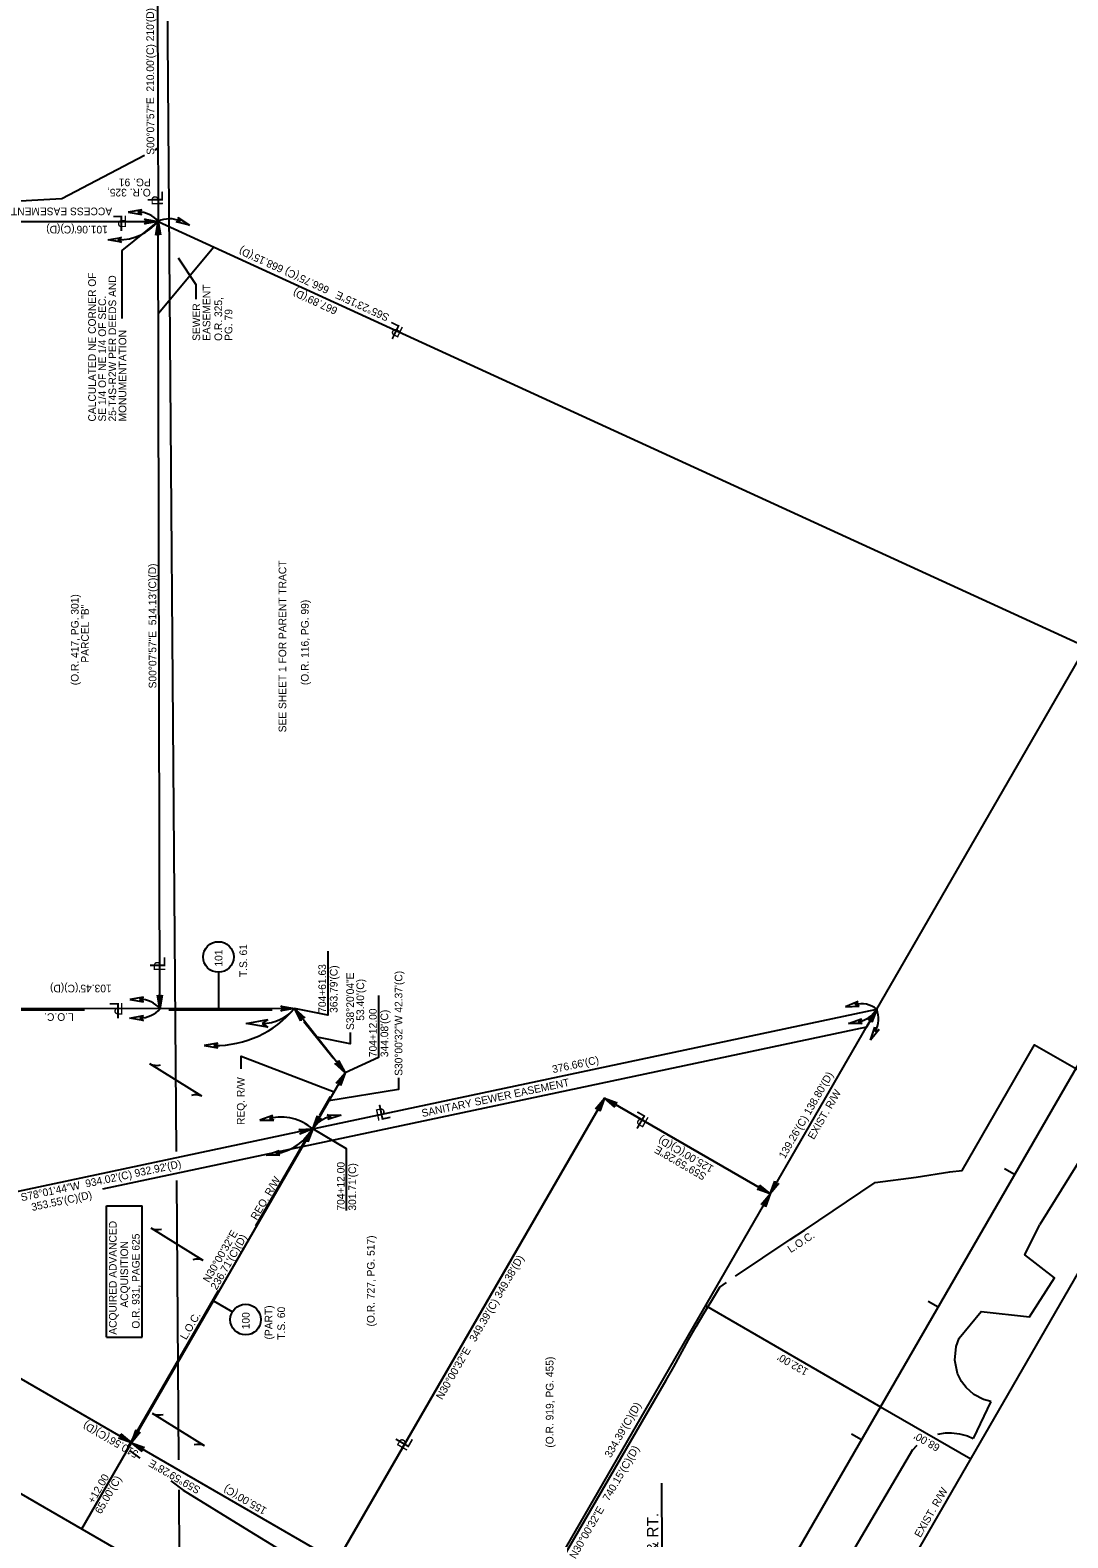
# Model space of a CAD drawing. Extents: x 2003883 to 2008298, y 399149 to 424047.
# Drawn here: x 2006444 to 2007122, y 402845 to 403830 of the extents above; entities that cross this region are included whole.
import ezdxf

# ---------------------------------------------------------------- set-up
doc = ezdxf.new("R2010")
doc.units = 0
for name, color, linetype in [('BaselineFlagLT', 7, 'Continuous'), ('BaselineSurvey', 7, 'Continuous'), ('BaselineTextWt1', 7, 'Continuous'), ('ConstLimits', 7, 'Continuous'), ('ConstLimitsText', 7, 'Continuous'), ('DataBoxWt1', 7, 'Continuous'), ('EaseLine_ep', 7, 'Continuous'), ('EaseLineText_ep', 7, 'Continuous'), ('GovTwpRgeLine_ep', 7, 'Continuous'), ('ParcelBubble100', 7, 'Continuous'), ('PropertyLine_ep', 7, 'Continuous'), ('PropertyLineHook_ep', 7, 'Continuous'), ('PropertyLineSymbol_ep', 7, 'Continuous'), ('PropertyLineText_ep', 7, 'Continuous'), ('RWandLA_StaTie', 7, 'Continuous'), ('RWandLA_Text', 7, 'Continuous'), ('RWandLA_Text_ep', 7, 'Continuous'), ('RWandLA_WidthArrow_ep', 7, 'Continuous'), ('RWLine', 7, 'Continuous'), ('RWLine_ep', 7, 'Continuous'), ('TextMisc', 7, 'Continuous')]:
    doc.layers.add(name, color=color, linetype=linetype)

msp = doc.modelspace()

# ---------------------------------------------------------------- linework, layer by layer
at = {"layer": 'BaselineFlagLT'}
msp.add_lwpolyline([(2006720.56, 402711.11), (2006857.82, 402747.44), (2006857.19, 402881.05)], dxfattribs=at)
at = {"layer": 'BaselineSurvey'}
for p, q in [((2006836.17, 402647.34), (2007687.69, 404121.69)), ((2007087.53, 403082.55), (2007081.03, 403086.3)), ((2007037.52, 402995.96), (2007031.02, 402999.71)), ((2006832.62, 402646.39), (2006307.25, 402949.82)), ((2006987.5, 402909.36), (2006981.01, 402913.11))]:
    msp.add_line(p, q, dxfattribs=at)
at = {"layer": 'ConstLimits'}
msp.add_line((2007072.12, 402934.43), (2007060.41, 402910.34), dxfattribs=at)
for points in [[(2006479.85, 403190), (2006332.39, 403189.92)], [(2006602.54, 403190.06), (2006534.92, 403190.03)], [(2006642.33, 403158.63), (2006623.31, 403182.39)], [(2006905.28, 403016.26), (2006940.92, 403040.2), (2006950.33, 403046.31), (2006996.49, 403077.39), (2006996.49, 403077.39), (2007023.29, 403080.85), (2007045.15, 403084.36), (2007045.15, 403084.36), (2007053.2, 403085.31), (2007100.64, 403167.34), (2007156.96, 403135.14), (2007104.02, 403049.96)], [(2006633.63, 403121.45), (2006640.69, 403133.68)], [(2006591.85, 403049.14), (2006627.04, 403110.05)], [(2007072.12, 402934.43), (2007067.25, 402935.81), (2007061.02, 402939.07), (2007055.84, 402943.62), (2007052.96, 402947.42), (2007050.32, 402952.69), (2007048.48, 402961.33), (2007049.37, 402970.38), (2007051.41, 402975.84), (2007065.81, 402993.18), (2007097.27, 402989.65), (2007113.66, 403015.13), (2007094.19, 403030.17), (2007104.02, 403049.96)], [(2006508.46, 402904.84), (2006567.38, 403006.81)], [(2006753.23, 402764.67), (2006753.23, 402764.67), (2006753.16, 402764.53), (2006859.92, 402948.4), (2006864.89, 402957.08), (2006874.47, 402974.64), (2006879.44, 402983.32), (2006884.6, 402991.89), (2006889.78, 403000.45), (2006894.93, 403009.02), (2006894.93, 403009.02), (2006899.45, 403012.18)], [(2007037.4, 402913.02), (2007042.49, 402913.89), (2007046.27, 402914.01), (2007051.65, 402913.4), (2007056.84, 402911.93), (2007060.41, 402910.34)], [(2006509.29, 402902.4), (2006516.17, 402897.33)], [(2006943.48, 402771.38), (2007021.09, 402903.08)], [(2007020.8, 402902.7), (2007023.97, 402905.97)], [(2006536.26, 402882.53), (2006544.33, 402876.58), (2006584.64, 402851.71), (2006635.87, 402820.4), (2006644.5, 402815.35), (2006653.07, 402810.19), (2006670.21, 402799.88), (2006678.78, 402794.72), (2006695.88, 402784.33), (2006704.42, 402779.13), (2006721.46, 402768.64), (2006729.97, 402763.38), (2006732.89, 402761.57)]]:
    msp.add_lwpolyline(points, dxfattribs=at)
at = {"layer": 'DataBoxWt1'}
for p, q in [((2006494.37, 402976.47), (2006494.37, 403062.21)), ((2006494.37, 403062.21), (2006517.5, 403062.21)), ((2006517.5, 402976.47), (2006517.5, 403062.21)), ((2006494.37, 402976.47), (2006517.5, 402976.47))]:
    msp.add_line(p, q, dxfattribs=at)
at = {"layer": 'EaseLine_ep'}
for p, q in [((2006465.05, 403720.02), (2006519.13, 403748.19)), ((2006526.13, 403751.83), (2006527.94, 403752.78)), ((2006302.99, 403711.05), (2006465.05, 403720.02)), ((2006528.19, 403645.01), (2006564.42, 403688.35)), ((2006997.46, 403190.54), (2006990.71, 403178.84)), ((2006990.71, 403178.84), (2006491.7, 403073.04))]:
    msp.add_line(p, q, dxfattribs=at)
at = {"layer": 'EaseLineText_ep'}
msp.add_lwpolyline([(2006552.87, 403654.27), (2006552.87, 403663.58), (2006541.27, 403680.98)], dxfattribs=at)
at = {"layer": 'GovTwpRgeLine_ep'}
for p, q in [((2006540.01, 403097.66), (2006528.59, 404563.92)), ((2006541.57, 402896.23), (2006540.15, 403078.81)), ((2006542.09, 402831.09), (2006541.73, 402876.66))]:
    msp.add_line(p, q, dxfattribs=at)
at = {"layer": 'ParcelBubble100'}
for centre in [(2006567.42, 403224.68), (2006585.2, 402987.87)]:
    msp.add_circle(centre, 10, dxfattribs=at)
at = {"layer": 'PropertyLine_ep'}
for p, q in [((2006527.56, 403915.01), (2006528.05, 403705.01)), ((2006426.99, 403705.03), (2006528.05, 403705.01)), ((2006528.05, 403705.01), (2007134.22, 403427.32)), ((2006529.24, 403190.88), (2006528.05, 403705.01)), ((2006629, 403112.41), (2006997.46, 403190.54)), ((2006644.81, 402829.92), (2006819.55, 403132.47)), ((2006819.57, 403132.47), (2006644.83, 402829.91)), ((2006819.55, 403132.47), (2006927.81, 403069.95)), ((2006927.82, 403069.95), (2006819.57, 403132.47)), ((2006629, 403112.41), (2006166.22, 403014.29))]:
    msp.add_line(p, q, dxfattribs=at)
at = {"layer": 'PropertyLineHook_ep'}
for p, q in [((2006556.61, 403133.7), (2006522.67, 403154.88)), ((2006557.45, 403026.43), (2006523.51, 403047.6)), ((2006558.39, 402905.47), (2006524.45, 402926.64))]:
    msp.add_line(p, q, dxfattribs=at)
for centre, start, end in [((2006526.89, 403163.43), 243.73036, 285.75196), ((2006552.49, 403125.1), 64.39507, 106.41667), ((2006527.73, 403056.15), 243.73036, 285.75196), ((2006553.33, 403017.83), 64.39507, 106.41667), ((2006528.67, 402935.2), 243.73036, 285.75196), ((2006554.27, 402896.87), 64.39507, 106.41667)]:
    msp.add_arc(centre, 9.54, start, end, dxfattribs=at)
at = {"layer": 'PropertyLineText_ep'}
for p, q in [((2006517.33, 403712.54), (2006508.43, 403711.04)), ((2006508.45, 403711.06), (2006517.35, 403709.51)), ((2006514.95, 403711.06), (2006517.35, 403712.56)), ((2006517.35, 403709.51), (2006514.95, 403711.06)), ((2006519.2, 403706.56), (2006528.05, 403705.01)), ((2006521.6, 403705.01), (2006519.2, 403706.56)), ((2006541.01, 403707.54), (2006548.46, 403702.52)), ((2006542.57, 403705.15), (2006541.01, 403707.54)), ((2006528.05, 403705.01), (2006519.2, 403703.46)), ((2006519.2, 403703.46), (2006521.6, 403705.01)), ((2006526.52, 403696.15), (2006528.05, 403705.01)), ((2006528.06, 403698.56), (2006526.52, 403696.15)), ((2006528.05, 403705.01), (2006529.62, 403696.16)), ((2006529.62, 403696.16), (2006528.06, 403698.56)), ((2006539.75, 403704.71), (2006542.57, 403705.15)), ((2006548.46, 403702.52), (2006539.75, 403704.71)), ((2006495.32, 403692.92), (2006504.17, 403694.47)), ((2006504.17, 403691.37), (2006495.32, 403692.92)), ((2006504.17, 403694.47), (2006501.77, 403692.92)), ((2006501.77, 403692.92), (2006504.17, 403691.37)), ((2006518.52, 403198.42), (2006509.62, 403196.92)), ((2006509.64, 403196.93), (2006518.54, 403195.38)), ((2006516.14, 403196.93), (2006518.54, 403198.43)), ((2006518.54, 403195.38), (2006516.14, 403196.93)), ((2006529.24, 403190.88), (2006527.67, 403199.72)), ((2006527.67, 403199.72), (2006529.22, 403197.33)), ((2006529.22, 403197.33), (2006530.77, 403199.73)), ((2006530.77, 403199.73), (2006529.24, 403190.88)), ((2006985.36, 403195.57), (2006977, 403192.17)), ((2006983.36, 403193.6), (2006985.38, 403195.58)), ((2006986.04, 403192.61), (2006983.36, 403193.6)), ((2006509.59, 403184.83), (2006518.44, 403186.38)), ((2006518.44, 403183.28), (2006509.59, 403184.83)), ((2006518.44, 403186.38), (2006516.04, 403184.83)), ((2006516.04, 403184.83), (2006518.44, 403183.28)), ((2006977.02, 403192.19), (2006986.04, 403192.61)), ((2006979.08, 403181.35), (2006987.55, 403184.33)), ((2006987.55, 403184.33), (2006985.44, 403182.4)), ((2006988.06, 403181.27), (2006979.08, 403181.35)), ((2006985.44, 403182.4), (2006988.06, 403181.27)), ((2006993.42, 403170.38), (2006996.27, 403178.9)), ((2006999, 403177.42), (2006993.42, 403170.38)), ((2006996.27, 403178.9), (2006996.49, 403176.05)), ((2006996.49, 403176.05), (2006999, 403177.42)), ((2006638.54, 403121.55), (2006647.52, 403121.34)), ((2006641.14, 403120.37), (2006638.54, 403121.55)), ((2006647.52, 403121.34), (2006639, 403118.48)), ((2006639, 403118.48), (2006641.14, 403120.37)), ((2006620.02, 403112.1), (2006629, 403112.41)), ((2006622.69, 403111.08), (2006620.02, 403112.1)), ((2006629, 403112.41), (2006620.66, 403109.06)), ((2006620.66, 403109.06), (2006622.69, 403111.08)), ((2006598.6, 403095.29), (2006607.09, 403098.22)), ((2006607.58, 403095.16), (2006598.6, 403095.29)), ((2006607.09, 403098.22), (2006604.96, 403096.31)), ((2006604.96, 403096.31), (2006607.58, 403095.16))]:
    msp.add_line(p, q, dxfattribs=at)
for centre, radius, start, end in [((2006515.59, 403695.2), 15.86, 38.19432, 92.38767), ((2006535.45, 403689.64), 17.06, 65.60387, 115.71277), ((2006502.01, 403727.04), 34.11, 269.65455, 319.76346), ((2006516.78, 403181.07), 15.86, 38.19432, 92.38767), ((2006987.43, 403178.26), 15.86, 50.74651, 104.93986), ((2006516.22, 403201.9), 17.06, 269.65455, 319.76346), ((2006982.81, 403199.27), 17.06, 279.10941, 329.21831), ((2006981.57, 403184.35), 17.06, 331.18389, 21.2928), ((2006643.52, 403103.47), 17.06, 98.27039, 148.37929), ((2006599.79, 403130.04), 34.11, 278.79159, 328.90049)]:
    msp.add_arc(centre, radius, start, end, dxfattribs=at)
at = {"layer": 'RWandLA_StaTie'}
msp.add_line((2006478.1, 402851.15), (2006510.61, 402907.43), dxfattribs=at)
at = {"layer": 'RWandLA_Text'}
for p, q in [((2006567.44, 403214.68), (2006567.47, 403190.93)), ((2006585.63, 403181.31), (2006599.79, 403183.79)), ((2006599.79, 403183.79), (2006595.95, 403181.31)), ((2006610.62, 403190.98), (2006608.21, 403192.53)), ((2006608.21, 403192.53), (2006617.07, 403190.99)), ((2006617.07, 403190.99), (2006608.22, 403189.43)), ((2006608.22, 403189.43), (2006610.62, 403190.98)), ((2006621.34, 403183.09), (2006617.07, 403190.99)), ((2006617.07, 403190.99), (2006623.77, 403185.01)), ((2006623.77, 403185.01), (2006621.07, 403185.93)), ((2006621.07, 403185.93), (2006621.34, 403183.09)), ((2006599.79, 403178.83), (2006585.63, 403181.31)), ((2006595.95, 403181.31), (2006599.79, 403178.83)), ((2006566.97, 403168.33), (2006558.07, 403166.83)), ((2006558.1, 403166.85), (2006567, 403165.3)), ((2006564.6, 403166.85), (2006567, 403168.35)), ((2006567, 403165.3), (2006564.6, 403166.85)), ((2006650.19, 403149.11), (2006643.48, 403155.09)), ((2006643.48, 403155.09), (2006646.19, 403154.17)), ((2006646.19, 403154.17), (2006645.91, 403157.01)), ((2006645.91, 403157.01), (2006650.19, 403149.11)), ((2006644.42, 403142.22), (2006650.19, 403149.11)), ((2006650.19, 403149.11), (2006647.1, 403140.67)), ((2006646.96, 403143.52), (2006644.42, 403142.22)), ((2006647.1, 403140.67), (2006646.96, 403143.52)), ((2006602.98, 403121.2), (2006594.53, 403118.04)), ((2006594.55, 403118.05), (2006603.59, 403118.22)), ((2006600.93, 403119.29), (2006603.01, 403121.22)), ((2006603.59, 403118.22), (2006600.93, 403119.29)), ((2006629, 403112.41), (2006632.08, 403120.85)), ((2006634.76, 403119.3), (2006629, 403112.41)), ((2006632.08, 403120.85), (2006632.22, 403118)), ((2006632.22, 403118), (2006634.76, 403119.3)), ((2006623.16, 403105.58), (2006629, 403112.41)), ((2006625.72, 403106.86), (2006623.16, 403105.58)), ((2006625.83, 403104), (2006625.72, 403106.86)), ((2006629, 403112.41), (2006625.83, 403104)), ((2006564.1, 403000.05), (2006576.54, 402992.87)), ((2006502.17, 402910.52), (2006505.02, 402910.66)), ((2006510.61, 402907.43), (2006502.17, 402910.52)), ((2006505.02, 402910.66), (2006503.72, 402913.2)), ((2006503.72, 402913.2), (2006510.61, 402907.43)), ((2006510.61, 402907.43), (2006513.69, 402915.87)), ((2006516.38, 402914.32), (2006510.61, 402907.43)), ((2006513.69, 402915.87), (2006513.83, 402913.02)), ((2006513.83, 402913.02), (2006516.38, 402914.32)), ((2006510.61, 402907.43), (2006519.05, 402904.35)), ((2006517.5, 402901.66), (2006510.61, 402907.43)), ((2006519.05, 402904.35), (2006516.19, 402904.21)), ((2006516.19, 402904.21), (2006517.5, 402901.66))]:
    msp.add_line(p, q, dxfattribs=at)
for points in [[(2006638.92, 403228.45), (2006638.92, 403186.63), (2006617.07, 403190.99)], [(2006672.04, 403199.43), (2006672.04, 403159.01), (2006650.19, 403149.11)], [(2006653.59, 403175.46), (2006653.59, 403167.98), (2006631.84, 403172.31)], [(2006582.27, 403151.68), (2006582.27, 403159.81), (2006643.03, 403136.71)], [(2006685.1, 403145.73), (2006685.1, 403138.25), (2006639.59, 403130.76)], [(2006651.03, 403059.06), (2006651.03, 403099.35), (2006629, 403112.41)]]:
    msp.add_lwpolyline(points, dxfattribs=at)
for centre, radius, start, end in [((2006564.98, 403235.06), 68.23, 269.65455, 319.76346), ((2006596.23, 403208.62), 27.29, 269.65455, 319.76346), ((2006608.25, 403088.42), 31.72, 49.15233, 103.34569)]:
    msp.add_arc(centre, radius, start, end, dxfattribs=at)
at = {"layer": 'RWandLA_Text_ep'}
for p, q in [((2006991.7, 403183.65), (2006997.46, 403190.54)), ((2006994.24, 403184.96), (2006991.7, 403183.65)), ((2006994.38, 403182.1), (2006994.24, 403184.96)), ((2006997.46, 403190.54), (2006994.38, 403182.1)), ((2006813.8, 403125.58), (2006819.57, 403132.47)), ((2006816.35, 403126.88), (2006813.8, 403125.58)), ((2006816.49, 403124.03), (2006816.35, 403126.88)), ((2006819.57, 403132.47), (2006816.49, 403124.03)), ((2006826.46, 403126.7), (2006819.57, 403132.47)), ((2006819.57, 403132.47), (2006828.01, 403129.38)), ((2006828.01, 403129.38), (2006825.16, 403129.24)), ((2006825.16, 403129.24), (2006826.46, 403126.7)), ((2006920.93, 403075.72), (2006927.82, 403069.95)), ((2006922.23, 403073.17), (2006920.93, 403075.72)), ((2006927.82, 403069.95), (2006930.9, 403078.39)), ((2006933.58, 403076.84), (2006927.82, 403069.95)), ((2006930.9, 403078.39), (2006931.04, 403075.53)), ((2006931.04, 403075.53), (2006933.58, 403076.84)), ((2006919.38, 403073.03), (2006922.23, 403073.17)), ((2006927.82, 403069.95), (2006919.38, 403073.03)), ((2006922.05, 403063.06), (2006927.82, 403069.95)), ((2006927.82, 403069.95), (2006924.73, 403061.51)), ((2006924.59, 403064.36), (2006922.05, 403063.06)), ((2006924.73, 403061.51), (2006924.59, 403064.36))]:
    msp.add_line(p, q, dxfattribs=at)
msp.add_lwpolyline([(2006504.6, 403641.67), (2006504.6, 403686), (2006528.05, 403705.01)], dxfattribs=at)
at = {"layer": 'RWandLA_WidthArrow_ep'}
for p, q in [((2006885.7, 402997.03), (2007000, 402931.01)), ((2007000, 402931.01), (2007058.89, 402897))]:
    msp.add_line(p, q, dxfattribs=at)
at = {"layer": 'RWLine'}
for p, q in [((2006617.07, 403190.99), (2006114.83, 403190.33)), ((2006650.19, 403149.11), (2006617.07, 403190.99)), ((2006510.61, 402907.43), (2006650.19, 403149.11)), ((2006510.61, 402907.43), (2006297.96, 403030.25)), ((2006740.08, 402774.9), (2006510.61, 402907.43))]:
    msp.add_line(p, q, dxfattribs=at)
at = {"layer": 'RWLine_ep'}
for p, q in [((2006760.57, 402780.38), (2007323.32, 403754.74)), ((2006296.18, 401576.43), (2007496.51, 403654.71))]:
    msp.add_line(p, q, dxfattribs=at)

# ---------------------------------------------------------------- texts
at = {"layer": 'BaselineTextWt1'}
msp.add_text('ACQUISITION LT. & RT.', height=7.5, rotation=90, dxfattribs=at).set_placement((2006854.87, 402750.81))
at = {"layer": 'ConstLimitsText'}
for rotation, p in [(180.07577, (2006472.91, 403187.97)), (33.01404, (2006941.26, 403031.24)), (59.9787, (2006546.34, 402974.27))]:
    msp.add_text('L.O.C.', height=5, rotation=rotation, dxfattribs=at).set_placement(p)
at = {"layer": 'EaseLineText_ep'}
for s, rotation, p in [('O.R. 325,', 179.9919, (2006523.2, 403726.32)), ('PG. 91', 179.9919, (2006523.2, 403732.99)), ('ACCESS EASEMENT', 179.9919, (2006498, 403714.06)), ('EASEMENT', 89.9919, (2006562.17, 403627.02)), ('SEWER', 89.9919, (2006555.49, 403627.02)), ('O.R. 325,', 89.9919, (2006569.83, 403626.99)), ('PG. 79', 89.9919, (2006576.51, 403626.99)), ('SANITARY SEWER EASEMENT', 11.9711, (2006700.73, 403120.13))]:
    msp.add_text(s, height=5, rotation=rotation, dxfattribs=at).set_placement(p)
at = {"layer": 'ParcelBubble100'}
for s, p in [('101', (2006570.02, 403218.38)), ('100', (2006587.8, 402981.57))]:
    msp.add_text(s, height=5, rotation=90, dxfattribs=at).set_placement(p)
at = {"layer": 'PropertyLineSymbol_ep'}
for s, height, rotation, p in [('L', 10, 91.09018, (2006531.3, 403717.57)), ('P', 7.5, 91.09018, (2006531.29, 403715.47)), ('L', 10, 179.99193, (2006505.76, 403708.82)), ('P', 7.5, 179.99193, (2006507.86, 403708.77)), ('L', 10, 154.1926, (2006686.86, 403636.52)), ('P', 7.5, 154.1926, (2006688.73, 403635.56)), ('L', 10, 89.85413, (2006532.76, 403217.45)), ('P', 7.5, 89.85413, (2006532.7, 403215.35)), ('L', 10, 180.08006, (2006503.46, 403194.65)), ('P', 7.5, 180.08006, (2006505.56, 403194.6)), ('P', 7.5, 11.9711, (2006670.98, 403117.62)), ('L', 10, 11.9711, (2006673.05, 403118.01)), ('L', 10, 149.99618, (2006847.39, 403120.46)), ('P', 7.5, 149.99618, (2006849.18, 403119.37)), ('L', 10, 59.99111, (2006691.1, 402903.35)), ('P', 7.5, 59.99111, (2006690.01, 402901.56))]:
    msp.add_text(s, height=height, rotation=rotation, dxfattribs=at).set_placement(p)
at = {"layer": 'PropertyLineText_ep'}
for s, rotation, p in [('S00°07\'57"E  210.00\'(C) 210\'(D)', 90.13252, (2006525.51, 403748.54)), ("101.06'(C)(D)", 179.96966, (2006495.21, 403702.16)), ('S65°23\'15"E   666.75\'(C) 668.15\'(D)', 155.38743, (2006679.53, 403644.07)), ('CALCULATED NE CORNER OF', 90, (2006487.35, 403574.35)), ('25-T4S-R2W PER DEEDS AND', 90, (2006500.61, 403574.35)), ("667.89'(D)", 155.38743, (2006645.74, 403648.45)), ('SE 1/4 OF NE 1/4 OF SEC.', 90, (2006493.98, 403574.35)), ('MONUMENTATION', 90, (2006507.25, 403574.35)), ('S00°07\'57"E  514.13\'(C)(D)', 90.13252, (2006526.9, 403400.08)), ('SEE SHEET 1 FOR PARENT TRACT', 90, (2006611.73, 403371.38)), ('(O.R. 417, PG. 301)', 90, (2006476.07, 403402.14)), ('PARCEL "B"', 90, (2006482.75, 403416.89)), ('(O.R. 116, PG. 99)', 90, (2006626.38, 403402.21)), ("103.45'(C)(D)", 180.07577, (2006497.69, 403206.62)), ("376.66'(C)", 11.9711, (2006786.05, 403148.8)), ('S78°01\'44"W  934.02\'(C) 932.92\'(D)', 11.9711, (2006438.84, 403065.17)), ("353.55'(C)(D)", 11.9711, (2006445.78, 403058.78)), ('(O.R. 727, PG. 517)', 90, (2006669.46, 402983.39)), ('N30°00\'32"E   349.39\'(C) 349.38\'(D)', 59.99111, (2006713.54, 402935.18)), ('(O.R. 919, PG. 455)', 90, (2006786.31, 402904.25))]:
    msp.add_text(s, height=5, rotation=rotation, dxfattribs=at).set_placement(p)
at = {"layer": 'RWandLA_Text'}
for s, rotation, p in [('T.S. 61', 90, (2006586.16, 403211.56)), ('704+61.63', 90, (2006637.72, 403188.2)), ("363.79'(C)", 90, (2006645.22, 403188.2)), ('S38°20\'04"E', 90, (2006655.98, 403176.99)), ('S30°00\'32"W 42.37\'(C)', 90, (2006687.61, 403147.07)), ("53.40'(C)", 90, (2006662.62, 403183.08)), ('704+12.00', 90, (2006670.84, 403159.26)), ("344.08'(C)", 90, (2006678.34, 403159.26)), ('REQ. R/W', 90, (2006584.51, 403114.97)), ('704+12.00', 90, (2006649.86, 403059.06)), ("301.71'(C)", 90, (2006657.36, 403059.06)), ('REQ. R/W', 59.62853, (2006592.41, 403052.46)), ('N30°00\'32"E', 59.99111, (2006561.31, 403011.63)), ("236.71'(C)(D)", 59.99111, (2006566.23, 403006.89)), ('(PART)', 90, (2006602.7, 402974.9)), ('T.S. 60', 90, (2006610.97, 402974.72)), ('S59°59\'28"E     510.56\'(C)(D)', 149.99111, (2006556.23, 402878.09)), ('+12.00', 59.99111, (2006485.96, 402867.32)), ("65.00'(C)", 59.99111, (2006490.68, 402860.49)), ("155.00'(C)", 149.99111, (2006599.45, 402864.53))]:
    msp.add_text(s, height=5, rotation=rotation, dxfattribs=at).set_placement(p)
at = {"layer": 'RWandLA_Text_ep'}
for s, rotation, p in [("139.26'(C) 138.80'(D)", 59.99111, (2006937.43, 403092.55)), ('EXIST. R/W', 59.99111, (2006956.41, 403105.06)), ("125.00'(C)(D)", 149.99111, (2006891.39, 403087.87)), ('S59°59\'28"E', 149.99111, (2006886.68, 403082.87)), ("132.00'", 149.99111, (2006953.3, 402955.27)), ("334.39'(C)(D)", 59.99111, (2006823.68, 402897.26)), ("68.00'", 149.99111, (2007039.29, 402905.72)), ('N30°00\'32"E   740.15\'(C)(D)', 59.99111, (2006800.68, 402831.25)), ('EXIST. R/W', 59.99111, (2007026.04, 402845.12))]:
    msp.add_text(s, height=5, rotation=rotation, dxfattribs=at).set_placement(p)
at = {"layer": 'TextMisc'}
for s, p in [('ACQUIRED ADVANCED', (2006500.92, 402978.03)), ('ACQUISITION', (2006508.42, 402995.71)), ('O.R. 931, PAGE 625', (2006515.92, 402981.98))]:
    msp.add_text(s, height=5, rotation=90, dxfattribs=at).set_placement(p)

doc.saveas('drawing.dxf')
